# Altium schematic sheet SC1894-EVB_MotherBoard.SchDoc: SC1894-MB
size A1; Organization: Maxim Integrated; Address1: 160 Rio Robles; Address2: San Jose, CA. 95134; Address3: U.S.A.; Address4: 408-601-1000; Revision: 2.0; SheetNumber: 1; SheetTotal: 1; PageSetup: Record=PageOptions¦CenterHorizontal=True¦CenterVertical=True¦PrintScale=0.52¦XCorrection=1.00¦YCorrection=1.00¦PrintKind=1¦BorderSize=5000000¦LeftOffset=0¦BottomOffset=0¦Orientation=2¦PaperLength=1000¦PaperWidth=1000¦Scale=100¦PaperSource=7¦PrintQuality=-4¦MediaType=1¦DitherType=10¦PaperKind=Tabloid¦PrintScaleMode=1
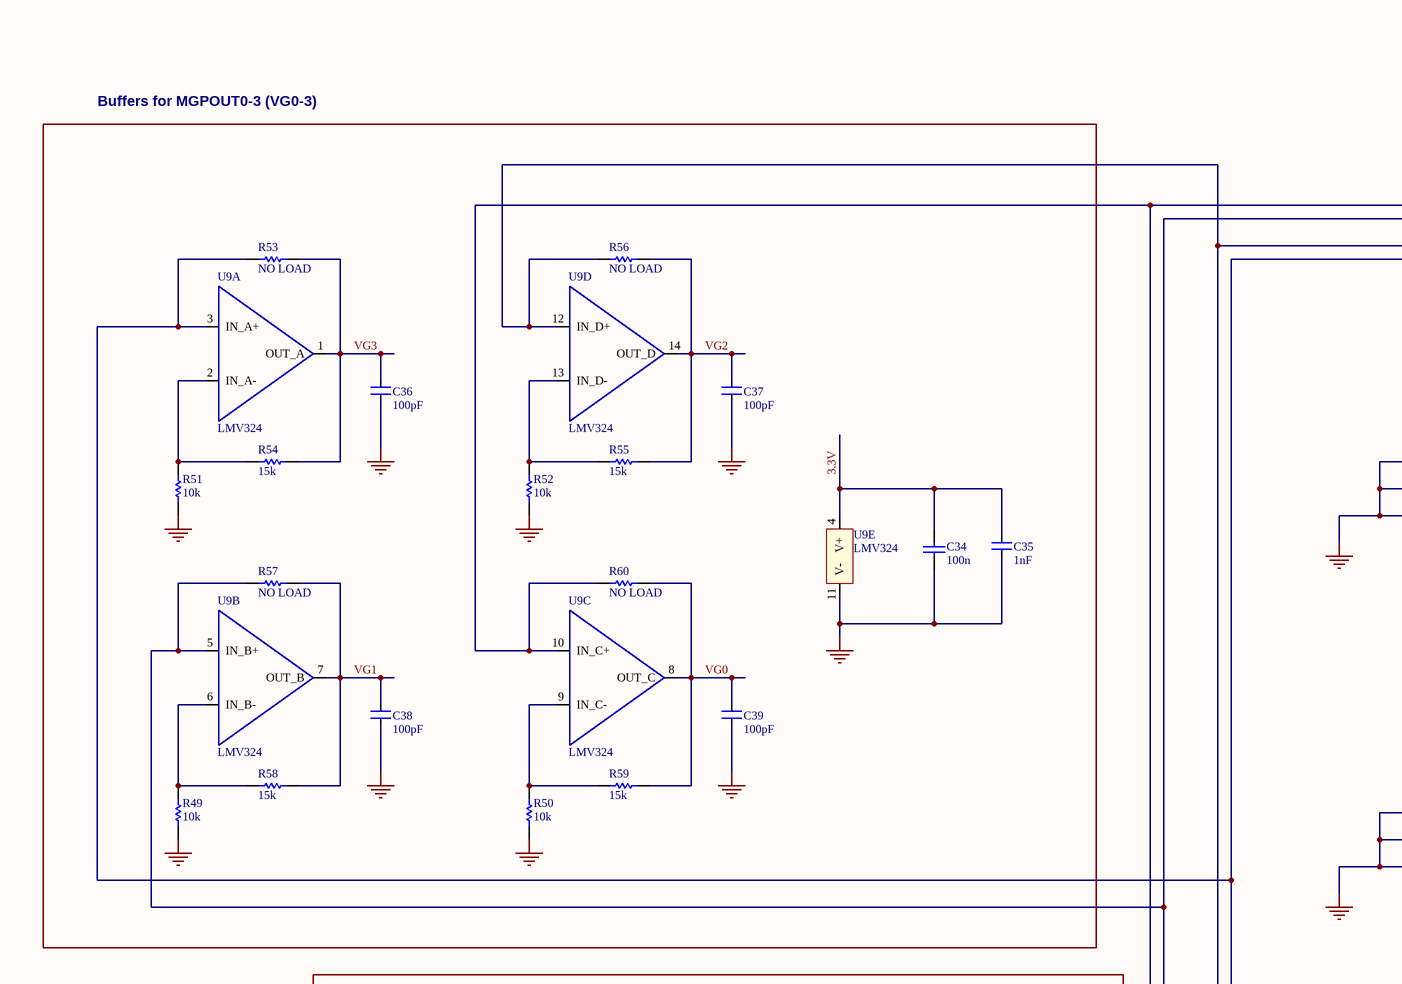
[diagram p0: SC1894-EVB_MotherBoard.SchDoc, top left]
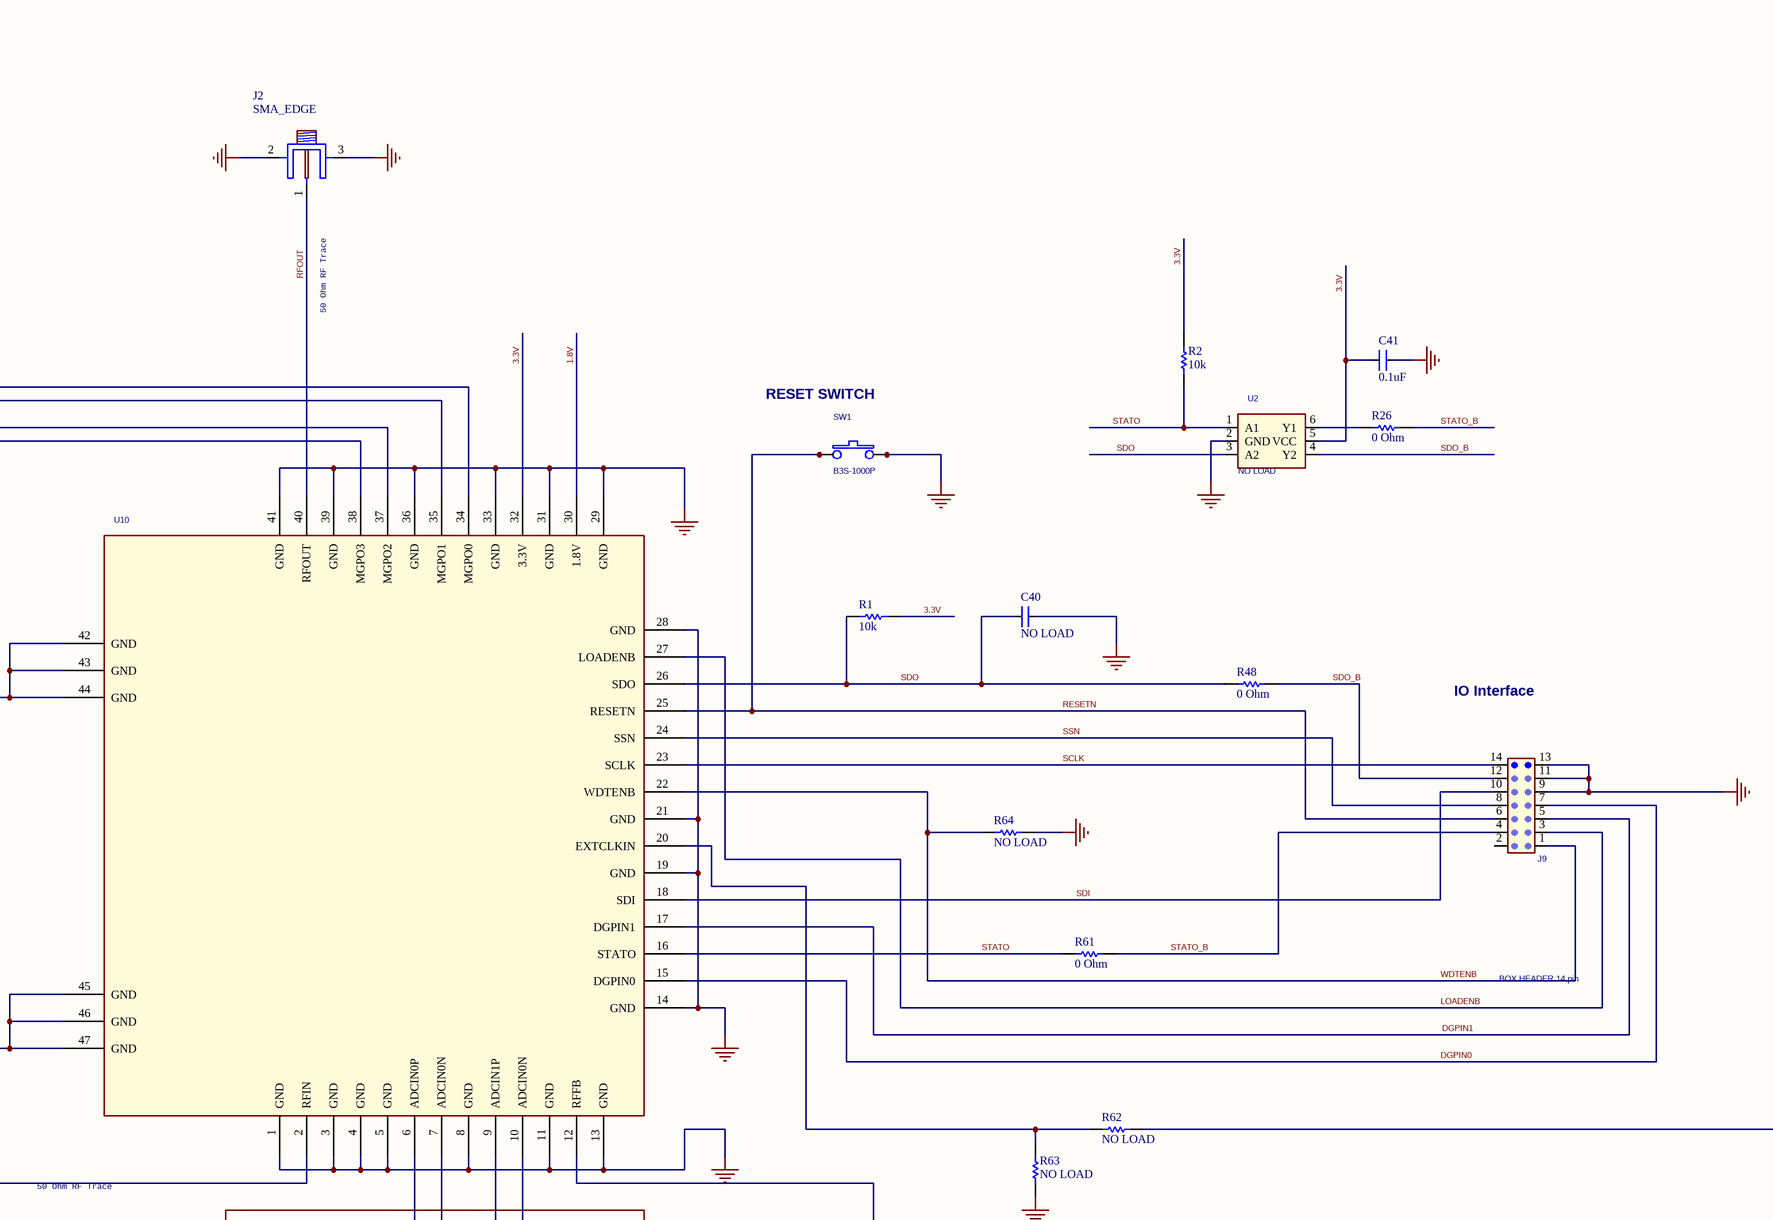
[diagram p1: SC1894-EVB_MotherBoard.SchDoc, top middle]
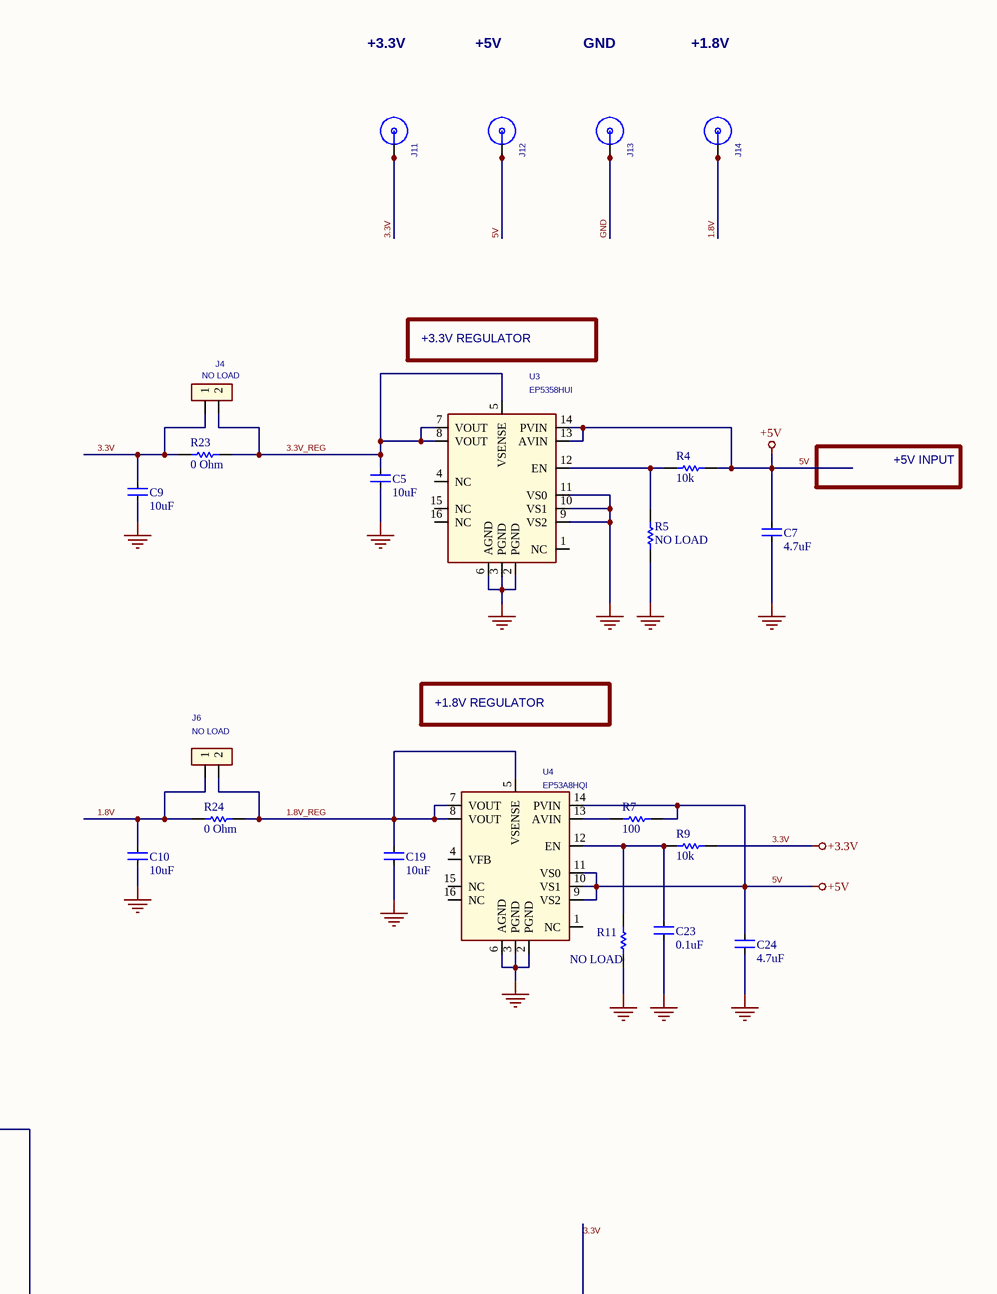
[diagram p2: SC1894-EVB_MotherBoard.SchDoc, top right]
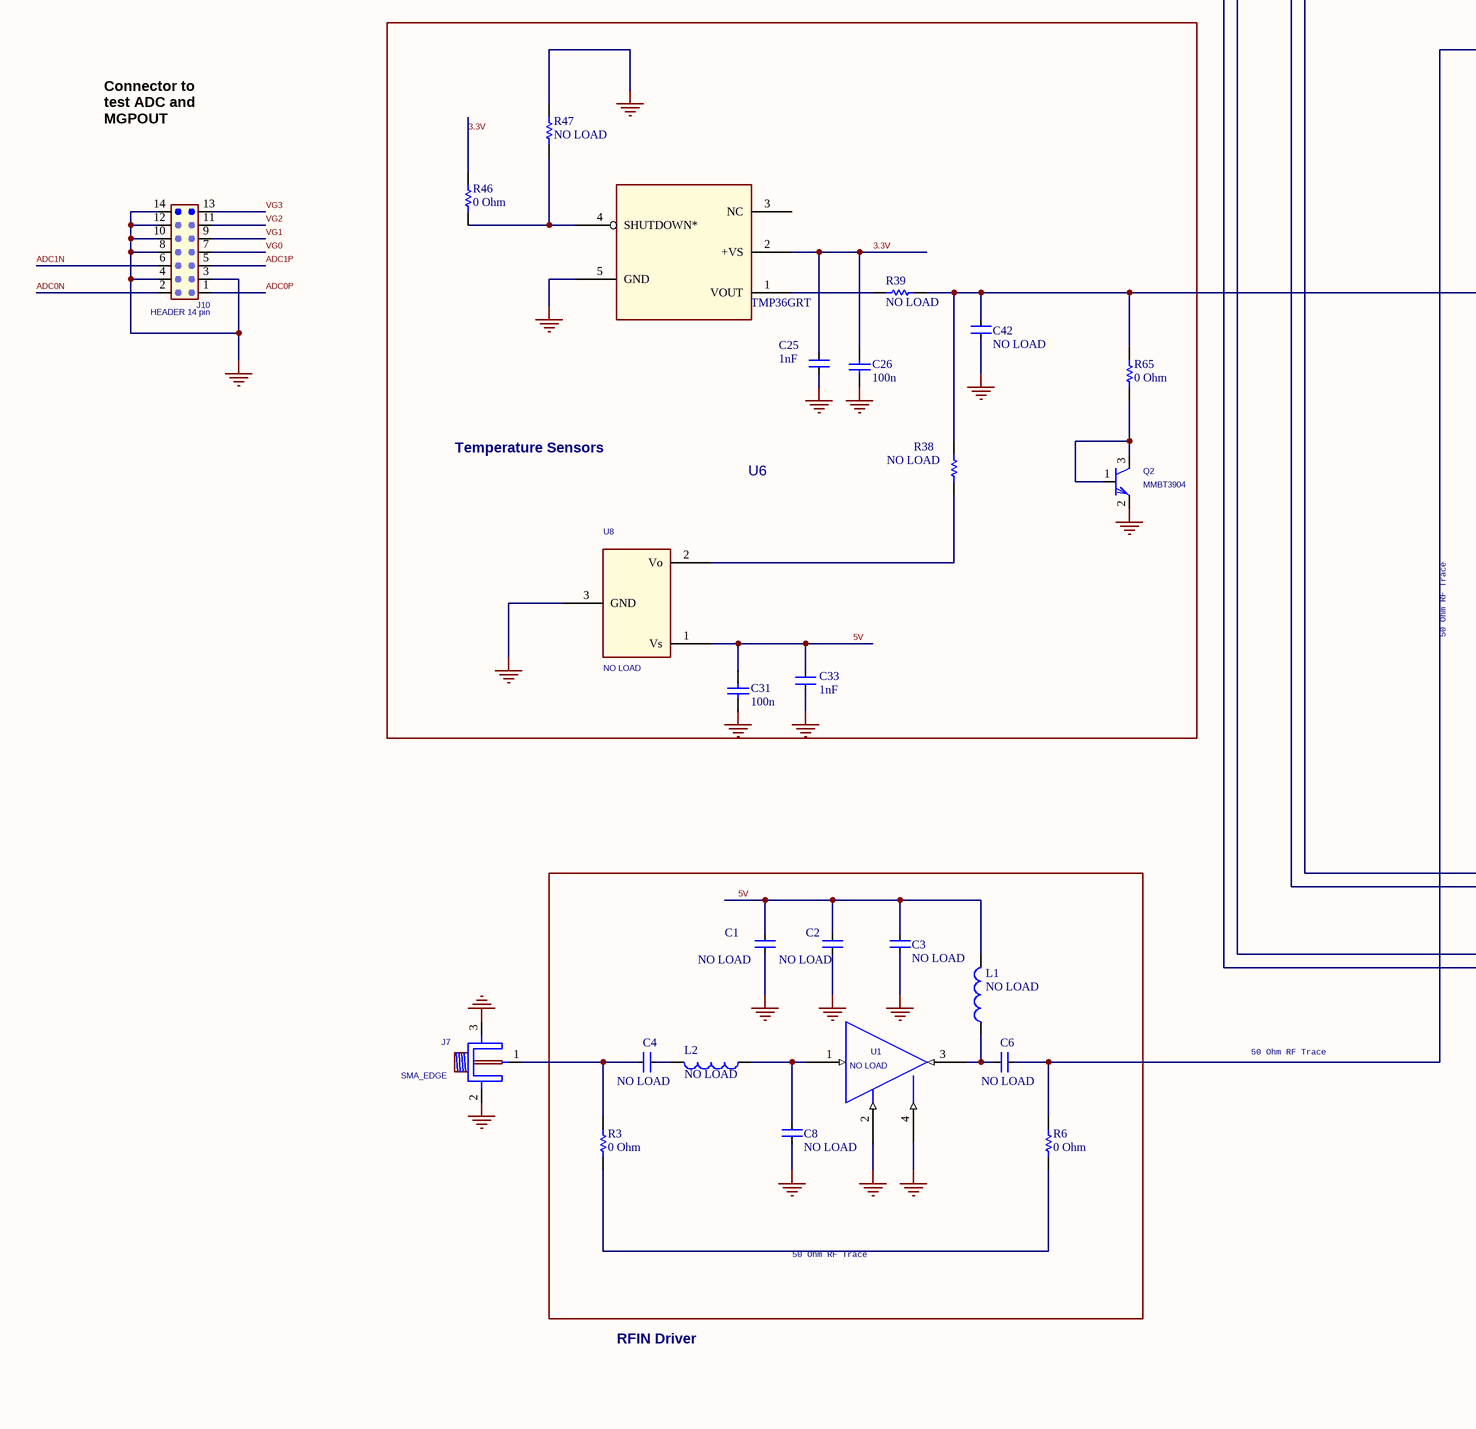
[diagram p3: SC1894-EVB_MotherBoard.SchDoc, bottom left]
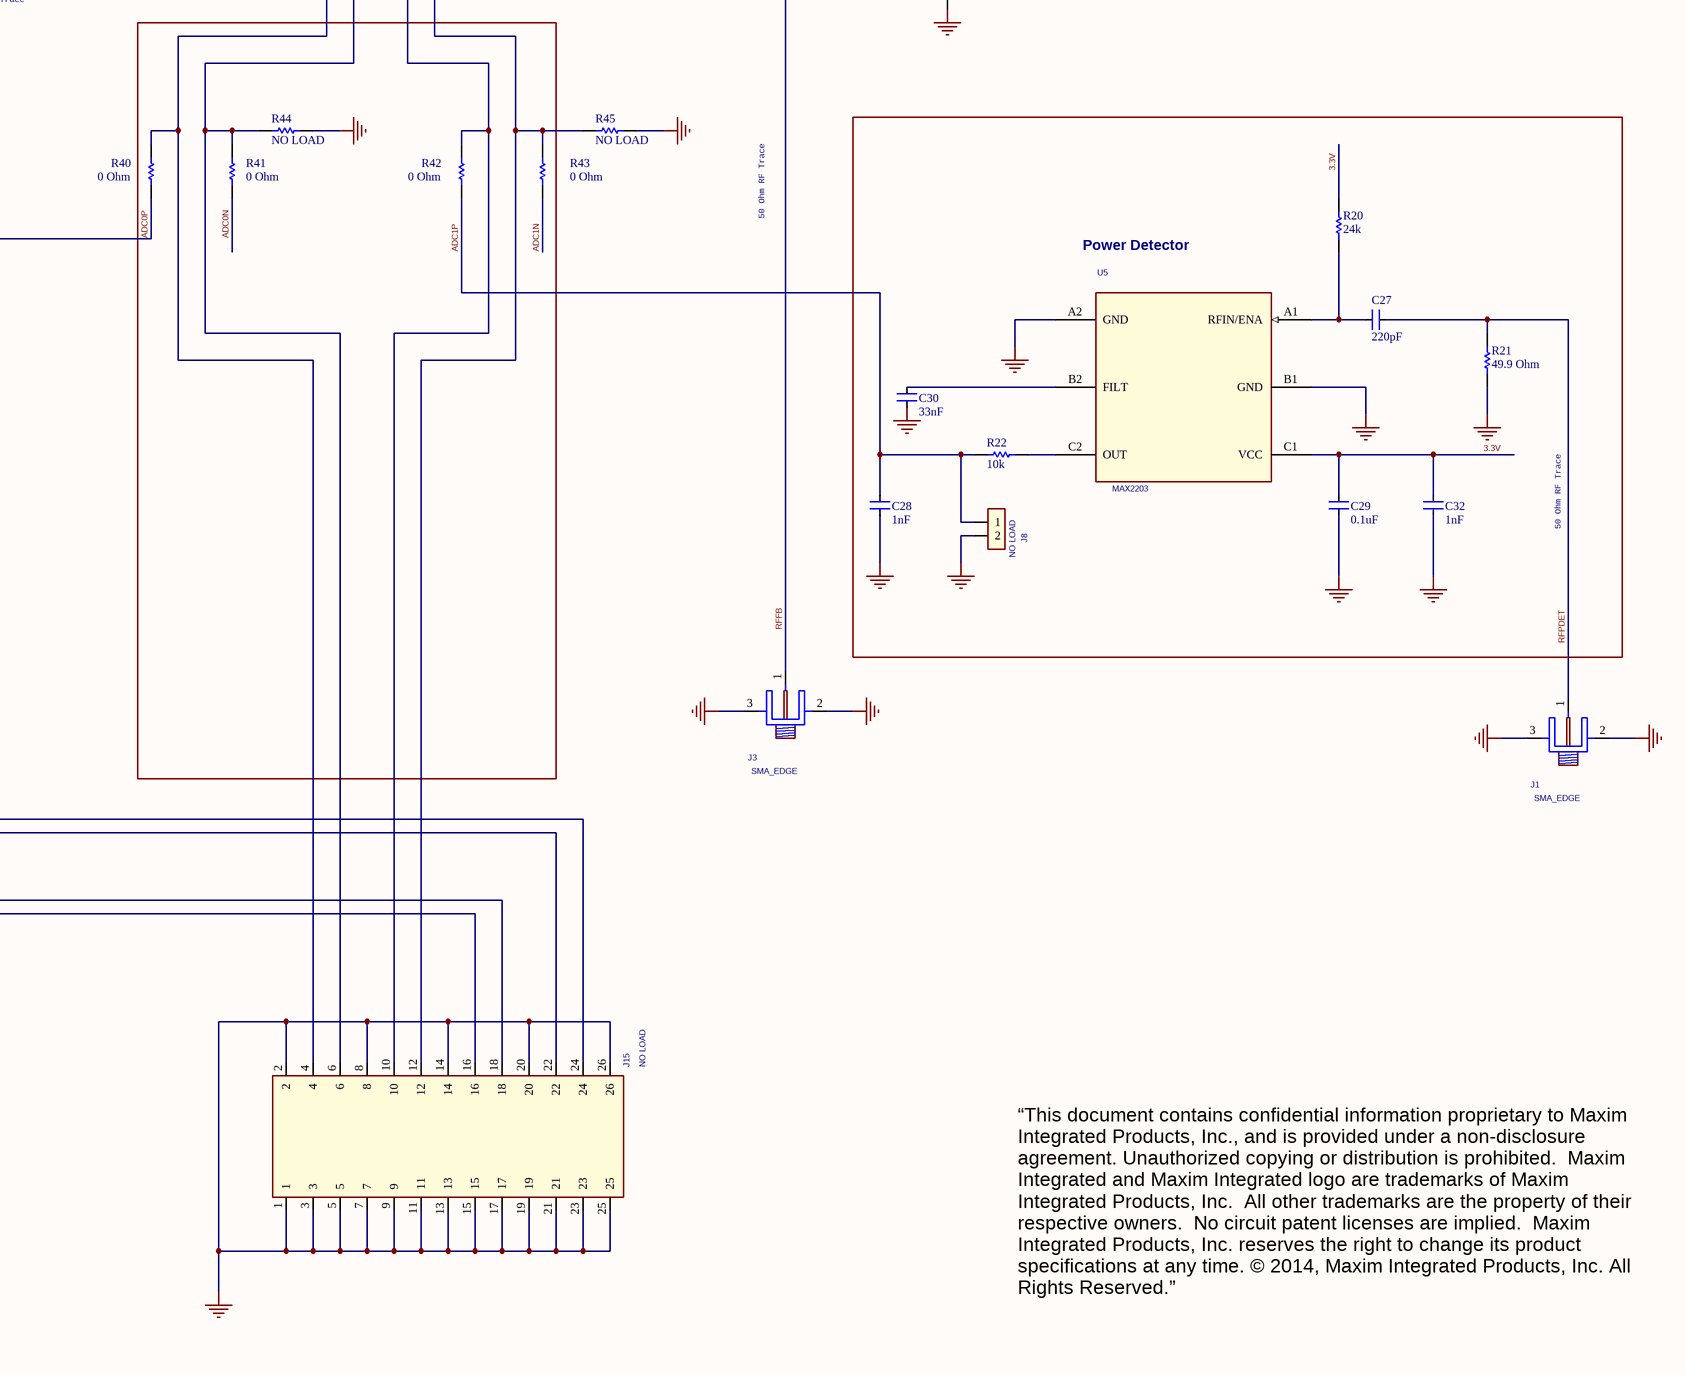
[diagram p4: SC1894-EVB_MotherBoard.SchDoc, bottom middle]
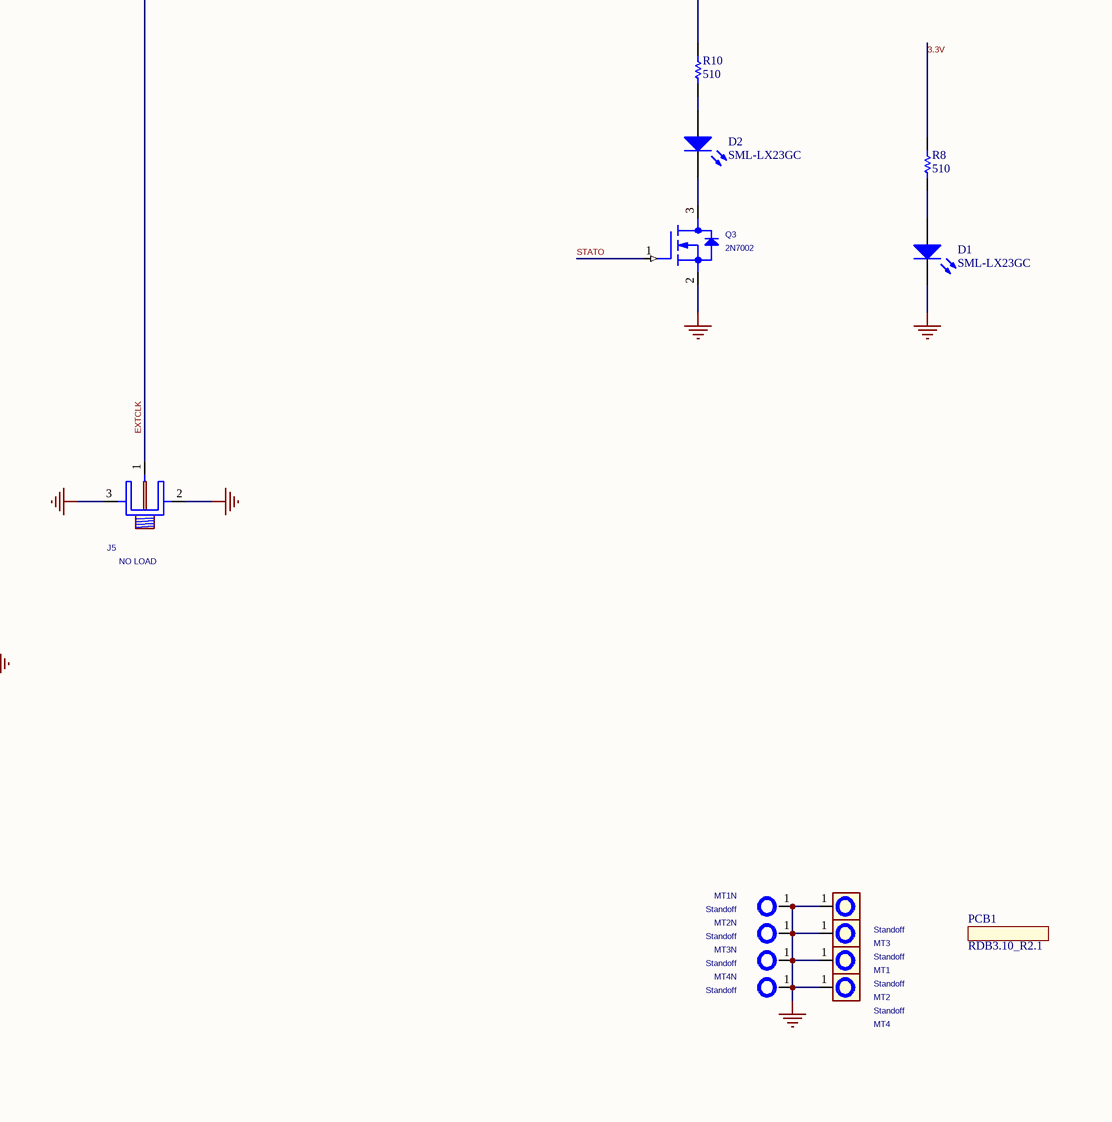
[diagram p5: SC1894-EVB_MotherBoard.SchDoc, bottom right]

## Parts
C1  NO LOAD  [0603 SMD]
C2  NO LOAD  [0402 SMD]
C3  NO LOAD  [0402 SMD]
C4  NO LOAD  [0402 SMD]
C5  10uF  [0805 SMD]
C6  NO LOAD  [0402 SMD]
C7  4.7uF  [0805 SMD]
C8  NO LOAD  [0402 SMD]
C9  10uF  [0805 SMD]
C10  10uF  [0805 SMD]
C19  10uF  [0805 SMD]
C23  0.1uF  [0402 SMD]
C24  4.7uF  [0805 SMD]
C25  1nF  [0402 SMD]
C26  100n  [1608[0603]]
C27  220pF  [0402 SMD]
C28  1nF  [0603 SMD]
C29  0.1uF  [0603 SMD]
C30  33nF  [0603 SMD]
C31  100n  [1608[0603]]
C32  1nF  [0402 SMD]
C33  1nF  [0402 SMD]
C34  100n  [1608[0603]]
C35  1nF  [0402 SMD]
C36  100pF  [0402 SMD]
C37  100pF  [0402 SMD]
C38  100pF  [0402 SMD]
C39  100pF  [0402 SMD]
C40  NO LOAD  [0402 SMD]
C41  0.1uF  [0402 SMD]
C42  NO LOAD  [0402 SMD]
D1  SML-LX23GC  [CD2012-0805]
D2  SML-LX23GC  [CD2012-0805]
J1  SMA_EDGE  [SMA EDGE]
J2  SMA_EDGE  [SMA EDGE]
J3  SMA_EDGE  [SMA EDGE]
J4  NO LOAD  [HDR2]
J5  NO LOAD  [SMA EDGE]
J6  NO LOAD  [HDR2]
J7  SMA_EDGE  [SMA EDGE]
J8  NO LOAD  [HDR2]
J9  BOX HEADER 14 pin  [HDR14-B]
J10  HEADER 14 pin  [HDR14-B]
J11  NO LOAD  [PWRJK-KOBI-164-62XX]  (value not drawn)
J12  UFL-R-SMT_1  [PWRJK-KOBI-164-62XX]  (value not drawn)
J13  UFL-R-SMT_2  [PWRJK-KOBI-164-62XX]  (value not drawn)
J14  NO LOAD  [PWRJK-KOBI-164-62XX]  (value not drawn)
J15  NO LOAD  [CON-ERF8-013-01-S-D-RA-L]
L1  NO LOAD  [0402 SMD]
L2  NO LOAD  [0402 SMD]
MT1  Standoff  [MTHOLE150X220]
MT1N  Standoff
MT2  Standoff  [MTHOLE150X220]
MT2N  Standoff
MT3  Standoff  [MTHOLE150X220]
MT3N  Standoff
MT4  Standoff  [MTHOLE150X220]
MT4N  Standoff
PCB1  RDB3.10_R2.1
Q2  MMBT3904  [TO92]
Q3  2N7002  [SOT23]
R1  10k  [0402 SMD]
R2  10k  [0402 SMD]
R3  0 Ohm  [0402 SMD]
R4  10k  [0402 SMD]
R5  NO LOAD  [0402 SMD]
R6  0 Ohm  [0402 SMD]
R7  100  [0402 SMD]
R8  510  [0402 SMD]
R9  10k  [0402 SMD]
R10  510  [0402 SMD]
R11  NO LOAD  [0402 SMD]
R20  24k  [0402 SMD]
R21  49.9 Ohm  [0402 SMD]
R22  10k  [0402 SMD]
R23  0 Ohm  [0603 SMD]
R24  0 Ohm  [0603 SMD]
R26  0 Ohm  [0402 SMD]
R38  NO LOAD  [0402 SMD]
R39  NO LOAD  [0402 SMD]
R40  0 Ohm  [0402 SMD]
R41  0 Ohm  [0402 SMD]
R42  0 Ohm  [0402 SMD]
R43  0 Ohm  [0402 SMD]
R44  NO LOAD  [0402 SMD]
R45  NO LOAD  [0402 SMD]
R46  0 Ohm  [0402 SMD]
R47  NO LOAD  [0402 SMD]
R48  0 Ohm  [0402 SMD]
R49  10k  [0402 SMD]
R50  10k  [0402 SMD]
R51  10k  [0402 SMD]
R52  10k  [0402 SMD]
R53  NO LOAD  [0402 SMD]
R54  15k  [0402 SMD]
R55  15k  [0402 SMD]
R56  NO LOAD  [0402 SMD]
R57  NO LOAD  [0402 SMD]
R58  15k  [0402 SMD]
R59  15k  [0402 SMD]
R60  NO LOAD  [0402 SMD]
R61  0 Ohm  [0402 SMD]
R62  NO LOAD  [0402 SMD]
R63  NO LOAD  [0402 SMD]
R64  NO LOAD  [0402 SMD]
R65  0 Ohm  [0402 SMD]
SW1  B3S-1000P  [SW-B3S-1000]
U1  NO LOAD  [SOT89]
U2  NO LOAD  [SC70]
U3  EP5358HUI  [QFN-EP53A8x]
U4  EP53A8HQI  [QFN-EP53A8x]
U5  MAX2203  [WLP-137X95-6]
U6  TMP36GRT  [SOT23-5]
U8  NO LOAD  [SOT23]
U9  LMV324  (parts A,B,C,D,E of 5)
U10  SC1894-DB1900A  [SCIN-RDB3]  (value not drawn)

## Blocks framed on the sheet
Buffers for MGPOUT0-3 (VG0-3): C34-C39 R49-R60 U9
Temperature Sensors: C25 C26 C31 C33 C42 Q2 R38 R39 R46 R47 R65 U6 U8
Power Detector: C27-C30 C32 J8 R20-R22 U5
50 Ohm RF Trace: C1-C4 C6 C8 L1 L2 R3 R6 U1

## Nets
3.3V: C9.1 C25.1 C26.2 C29.1 C32.1 C34.2 C35.1 C41.1 J4.1 J11.1 J11.2 R1.2 R2.2 R8.2 R9.2 R10.2 R20.2 R23.1 R46.2 U2.5(VCC) U5.C1(VCC) U6.2(+VS) U9.4(V+) U10.32(3.3V)  [also labelled +3.3V]
5V: C1.1 C2.1 C3.1 C7.1 C24.1 C31.2 C33.1 J12.1 J12.2 L1.2 R4.2 R7.2 U3.13(AVIN) U3.14(PVIN) U4.9(VS2) U4.10(VS1) U4.11(VS0) U4.14(PVIN) U8.1(Vs)  [also labelled +5V]
GND: C1.2 C2.2 C3.2 C5.2 C7.2 C8.1 C9.2 C10.2 C19.2 C23.2 C24.2 C25.2 C26.1 C28.2 C29.2 C30.2 C31.1 C32.2 C33.2 C34.1 C35.2 C36.2 C37.2 C38.2 C39.2 C40.2 C41.2 C42.2 D1.2(K) J1.2(GND) J1.3(GND) J2.2(GND) J2.3(GND) J3.2(GND) J3.3(GND) J5.2(GND) J5.3(GND) J7.2(GND) J7.3(GND) J8.2 J9.9 J9.11 J9.13 J10.3 J10.4 J10.8 J10.10 J10.12 J10.14 J13.1 J13.2 J15.1 J15.2 J15.3 J15.5 J15.7 J15.8 J15.9 J15.11 J15.13 J15.14 J15.15 J15.17 J15.19 J15.20 J15.21 J15.23 J15.25 J15.26 J15.27(GND) J15.28(GND) J15.31(GND) J15.32(GND) MT1.1 MT1N.1 MT2.1 MT2N.1 MT3.1 MT3N.1 MT4.1 MT4N.1 Q2.2(e) Q3.2(SOURCE) R5.1 R11.1 R21.1 R44.1 R45.1 R47.2 R49.1 R50.1 R51.2 R52.2 R63.1 R64.2 SW1.3 SW1.4 U1.2(GND) U1.4(GND) U2.2(GND) U3.2(PGND) U3.3(PGND) U3.6(AGND) U3.9(VS2) U3.10(VS1) U3.11(VS0) U4.2(PGND) U4.3(PGND) U4.6(AGND) U5.A2(GND) U5.B1(GND) U6.5(GND) U8.3(GND) U9.11(V-) U10.1(GND) U10.3(GND) U10.4(GND) U10.5(GND) U10.8(GND) U10.11(GND) U10.13(GND) U10.14(GND) U10.19(GND) U10.21(GND) U10.28(GND) U10.29(GND) U10.31(GND) U10.33(GND) U10.36(GND) U10.39(GND) U10.41(GND) U10.42(GND) U10.43(GND) U10.44(GND) U10.45(GND) U10.46(GND) U10.47(GND) U10.48(GND) U10.49(GND) U10.50(GND) U10.51(GND) U10.52(GND) U10.53(GND) U10.54(GND) U10.55(GND) U10.56(GND) U10.57(GND) U10.58(GND) U10.59(GND) U10.60(GND) U10.61(GND) U10.62(GND) U10.63(GND)
1.8V: C10.1 J6.1 J14.1 J14.2 R24.1 U10.30(1.8V)
1.8V_REG: C19.1 J6.2 R24.2 U4.5(VSENSE) U4.7(VOUT) U4.8(VOUT)
3.3V_REG: C5.1 J4.2 R23.2 U3.5(VSENSE) U3.7(VOUT) U3.8(VOUT)
ADC0N: J10.2 R41.1
ADC0P: C42.1 J10.1 R38.2 R39.1 R40.1 R65.2
ADC1N: J10.6 R43.1
ADC1P: C28.1 J8.1 J10.5 R22.1 R42.1
DGPIN0: J9.7 U10.15(DGPIN0)
DGPIN1: J9.5 U10.17(DGPIN1)
EXTCLK: J5.1(SIG) R62.2
LOADENB: J9.3 U10.27(LOADENB)
RESETN: J9.6 SW1.1 SW1.2 U10.25(RESETN)
RFFB: J3.1(SIG) U10.12(RFFB)
RFOUT: J2.1(SIG) U10.40(RFOUT)
RFPDET: C27.2 J1.1(SIG) R21.2
SCLK: J9.14 U10.23(SCLK)
SDI: J9.10 U10.18(SDI)
SDO: C40.1 R1.1 R48.1 U2.3(A2) U10.26(SDO)
SDO_B: J9.12 R48.2 U2.4(Y2)
SSN: J9.8 U10.24(SSN)
STATO: Q3.1(GATE) R2.1 R61.1 U2.1(A1) U10.16(STATO)
STATO_B: J9.4 R26.2 R61.2
VG0: C39.1 J10.7 R59.1 R60.1 U9.8(OUT_C)
VG1: C38.1 J10.9 R57.2 R58.2 U9.7(OUT_B)
VG2: C37.1 J10.11 R55.1 R56.1 U9.14(OUT_D)
VG3: C36.1 J10.13 R53.2 R54.2 U9.1(OUT_A)
WDTENB: J9.1 R64.1 U10.22(WDTENB)
NetC4_1: C4.1 J7.1(SIG) R3.2
NetC4_2: C4.2 L2.2
NetC6_1: C6.1 R6.2 U10.2(RFIN)
NetC6_2: C6.2 L1.1 U1.3(OUT)
NetC8_2: C8.2 L2.1 U1.1(IN)
NetC23_1: C23.1 R9.1 R11.2 U4.12(EN)
NetC27_1: C27.1 R20.1 U5.A1(RFIN/ENA)
NetC30_1: C30.1 U5.B2(FILT)
NetD1_1: D1.1(A) R8.1
NetD2_1: D2.1(A) R10.1
NetD2_2: D2.2(K) Q3.3(DRAIN)
NetJ15_4: J15.4 R40.2 U10.6(ADCIN0P)
NetJ15_6: J15.6 R41.2 R44.2 U10.7(ADCIN0N)
NetJ15_10: J15.10 R42.2 U10.9(ADCIN1P)
NetJ15_12: J15.12 R43.2 R45.2 U10.10(ADCIN0N)
NetJ15_16: J15.16 R60.2 U9.10(IN_C+) U10.34(MGPO0)
NetJ15_18: J15.18 R57.1 U9.5(IN_B+) U10.35(MGPO1)
NetJ15_22: J15.22 R56.2 U9.12(IN_D+) U10.37(MGPO2)
NetJ15_24: J15.24 R53.1 U9.3(IN_A+) U10.38(MGPO3)
NetQ2_1: Q2.1(b) Q2.3(c) R65.1
NetR3_1: R3.1 R6.1
NetR4_1: R4.1 R5.2 U3.12(EN)
NetR7_1: R7.1 U4.13(AVIN)
NetR22_2: R22.2 U5.C2(OUT)
NetR26_1: R26.1 U2.6(Y1)
NetR38_1: R38.1 U8.2(Vo)
NetR39_2: R39.2 U6.1(VOUT)
NetR46_1: R46.1 R47.1 U6.4(SHUTDOWN*)
NetR49_2: R49.2 R58.1 U9.6(IN_B-)
NetR50_2: R50.2 R59.2 U9.9(IN_C-)
NetR51_1: R51.1 R54.1 U9.2(IN_A-)
NetR52_1: R52.1 R55.2 U9.13(IN_D-)
NetR62_1: R62.1 R63.2 U10.20(EXTCLKIN)

Not connected (* = marked no-connect by the designer): J9 2; U3 1(NC) 4(NC) 15(NC) 16(NC); U4 1(NC) 4(VFB) 15(NC) 16(NC); U6 3(NC)

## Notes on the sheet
- +3.3V
- +5V
- GND
- +1.8V
- 50 Ohm RF Trace
- (near SW1) RESET SWITCH
- +3.3V REGULATOR
- +5V INPUT
- IO Interface
- +1.8V REGULATOR
- Connector to
  test ADC and
  MGPOUT
- RFIN Driver
- “This document contains confidential information proprietary to Maxim Integrated Products, Inc., and is provided under a non-disclosure agreement. Unauthorized copying or distribution is prohibited.  Maxim Integrated and Maxim Integrated logo are trademarks of Maxim Integrated Products, Inc.  All other trademarks are the property of their respective owners.  No circuit patent licenses are implied.  Maxim Integrated Products, Inc. reserves the right to change its product specifications at any time. © 2014, Maxim Integrated Products, Inc. All Rights Reserved.”

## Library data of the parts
C1 = Cap No Load 0603: 0603 Cap No Load
C2-C4 C6 C8 C40 C42 = Cap No Load 0402: 0402 Cap No Load
C5 C9 C10 C19 = Cap 10uF 0805
C7 C24 = Cap 4.7uF 0805
C23 C41 = Cap 0.1uF 0402
C25 C32 C33 C35 = Cap 1000pF: 1000pF 0402
C26 C31 C34 = 100n: 100nF 0603 ceramic capacitor
C27 = Cap 220pF 0402: 220pF 0402
C28 = Cap 1nF 0603: 1nF 0603
C29 = Cap 0.1uF 0603
C30 = Cap 33nF 0603: 33nF 0603
C36-C39 = 100pF 0402: 100pF 0402 Murata Capacitor; Manufacturer Part Number 1: GRM1555C1H101JZ01D
D1 D2 = SML-LX23GC: Green LED
J1-J3 J5 J7 = SMA_EDGE: SMA RECEPTACLE END LAUNCH,  Emerson 142-0701-801
J4 J6 J8 = CON28L: Two Pin Header / Jumper
J9 = JMP_14: PART: BOX HEADER 14PIN, 2X6, 0.1", FCI 10056844-114LF
J10 = HEADER 14 pin: 14 Pin Header
J11 J12 J14 = UFL-R-SMT_1: Banana Supply Connector  Red
J13 = UFL-R-SMT_2: Banana Supply Connector Black
J15 = ERF8-013-01-S-D-RA-L: Part: CONNECTOR, SAMTEC; Manufacturer 1: Samtec
L1 L2 = IND NL 0402: NO LOAD INDUCTOR 0402
MT1-MT4 = CON1_0: Mounting Hole  / STANDOFF
MT1N MT2N MT3N MT4N = CON1_1: Mounting Hole  / STANDOFF
PCB1 = RDB3.10_R2.1: SC1894-MB (RDB3.10_R2.1)
Q2 = MMBT3904: Part: FAIRCHILD MMBT3904; COMPONENT: 2N3904
Q3 = 2N7002/SOT_0: PART: MOSFET N-CH 60V 115MA SOT23, Fairchild
R1 R2 R4 R9 R22 R49-R52 = 10k Ohm 0402
R3 R6 R26 R40-R43 R46 R48 R61 R64 R65 = 0 Ohm 0402
R5 R11 R38 R39 R44 R45 R47 R53 R56 R57 R60 R62 R63 = RES NL 0402: NO LOAD RESISTOR 0402
R7 = RES 100 0402: RESISTOR 100 Ohm 0402
R8 R10 = RES 510 0402: RESISTOR 510 Ohm 0402
R20 = RES 24k 0402: RESISTOR 24k Ohm 0402
R21 = 49.9 Ohm 0402
R23 R24 = 0 Ohm 0603
R54 R55 R58 R59 = 15k Ohm 0402
SW1 = SW PUSHBUTTON_0: Pushbutton Switch; Part: SW, PUSH, Omronm B3S-1000P
U1 = MGA30889: RF Amplifier; PART: AMPLIFIER, MGA30889, AVAGO, 15dB, 1500-2600MHz, 5V, SOT89
U2 = NC7WZ07: IC Buffer; PART: IC BUFFER UHS DUAL SC70-6, FAIRCHILD
U3 = EP5358HUI: Enpirion Voltage Regulator; Part Substitution Allowed?: No
U4 = EP53A8HQI: Enpirion Voltage Regulator; Part Substitution Allowed?: No
U5 = MAX2203: RF Power Detector
U6 = TMP36GRT: Temp Sensor; SlotXofY: SYM 1 OF 1
U8 = LM50C: Temp Sensor
U9 = LMV324QDR: Quad OpAmp LMV324QDR; Manufacturer 1: Texas Instruments
U10 = SC1894-DB1900A: Daughterboard: SC1894-DB1900A; BOM Rev: 2.1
